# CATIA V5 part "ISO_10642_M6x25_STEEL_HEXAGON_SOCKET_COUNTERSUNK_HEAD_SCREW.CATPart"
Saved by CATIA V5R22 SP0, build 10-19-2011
Part number: ISO 10642 SCREW M6x25 STEEL HEXAGON SOCKET COUNTERSUNK HEAD
Publications: "Mating Edge", "Axis"
Bounding box of the stored display mesh (mm): x -25.42 to 0, y -6.719 to 6.719, z -6.714 to 6.714
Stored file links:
  D:\PER\CAO_PER_MODIF_2025\CAO_PER_pick&place_2024P\Sous_Ensemble_Boite\ISO_10642_M6x25_STEEL_HEXAGON_SOCKET_COUNTERSUNK_HEAD_SCREW.CATPart
  C:\Program Files\Dassault Systemes\B22\win_b64\startup\components\MechanicalStandardParts\EN_Standards\Design_Tables\EN_ISO_10642_HEXAGON_SOCKET_COUNTERSUNK_SCREW.txt
  C:\Program Files\Dassault Systemes\B22\win_b64\startup\components\MechanicalStandardParts\ISO_Standards\Design_Tables\ISO_10642_HEXAGON_SOCKET_COUNTERSUNK_SCREW.txt
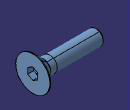
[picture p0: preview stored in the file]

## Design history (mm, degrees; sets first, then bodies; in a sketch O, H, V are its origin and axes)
Parameters
  l_length_nom = 25 mm
  b_ref = 24
  l_length_min = 24.58 mm
  l_length_max = 25.42 mm
  dk_head_dia_max = 13.44 mm
  dk_head_dia_min = 11.34 mm
  ls = 6.72 mm
  k_hed_depth = 3.72 mm
  r = 0.25 mm
  s_across_flats = 4 mm
  t_insert_depth = 2.2 mm
  d_dia = 6 mm
  threading = 18.28 mm
  p_pitch = 1 mm
Body1 "PartBody" (main body)
  Sketch1 on zx-plane, origin (0, 0, 0), H (-1, 0, 0), V (0, 0, 1)
    line L1 (0, 6.72) -> (0.3333, 6.72)
    point P2 (0.3333, 6.72)
    line L2 (0.3333, 6.72) -> (4.0533, 3)
    line L3 (4.0533, 3) -> (6.72, 3)
    line L4 (6.72, 3) -> (6.72, 2.9268)
    point P5 (6.72, 2.9268)
    line L5 (6.72, 2.9268) -> (24.8787, 2.9268)
    point P6 (24.8787, 2.9268)
    line L6 (24.8787, 2.9268) -> (25.42, 2.3855)
    axis line L7 (-30, 0) -> (125, 0)
    line L8 (25.42, 2.3855) -> (25.42, 0)
    point P10 (25.42, 0)
    line L9 (0, 6.72) -> (0, 0)
    distance L9 P5 = 6.72 {= ls}
    distance L9 L8 = 25.42 {= l_length_max}
    angle L5 L6 = 45
    distance L5 L7 = 2.9268 {= d_dia /2.05}
    distance L3 L7 = 3 {= d_dia  /2}
    angle L7 L2 = 45
    distance L1 L7 = 6.72 {= dk_head_dia_max /2}
    distance L9 P2 = 0.3333 {= p_pitch /3}
    distance P6 L8 = 0.5413 {= p_pitch *0.5413}
    horizontal: L1 H, L3 H, L5 H, L7 H
    vertical: L4 V, L9 V
    fix: L7
    coincidence: P10 L7
  Shaft1: profile Sketch1, axis Sketch1.L7, angle 360
  Body2
    Sketch2 on face of Shaft1, origin (0, 0, 0), H (0, 1, 0), V (0, 0, 1)
      point P1 (2, -1.1547)
      point P2 (2, 1.1547)
      point P3 (0, 2.3094)
      point P4 (-2, 1.1547)
      point P5 (-2, -1.1547)
      point P6 (0, -2.3094)
      point P7 (2, 0)
      line L1 (2, -1.1547) -> (2, 1.1547)
      line L2 (2, 1.1547) -> (0, 2.3094)
      line L3 (0, 2.3094) -> (-2, 1.1547)
      line L4 (-2, 1.1547) -> (-2, -1.1547)
      line L5 (-2, -1.1547) -> (0, -2.3094)
      line L6 (0, -2.3094) -> (2, -1.1547)
      construction line L7 (0, 0) -> (2, 0)
      construction circle A1 centre (0, 0) radius 2.3094
      construction arc A2 centre (-2, -1.1547) radius 2.3094 from (-2, 1.1547) to (0, -2.3094) cw
      construction arc A3 centre (2, 1.1547) radius 2.3094 from (0, 2.3094) to (2, -1.1547) ccw
      point P8 (-2, -1.1547)
      point P9 (2, 1.1547)
      distance L1 L4 = 4 {= s_across_flats}
      horizontal: L7 H
      coincidence: A1 P1, A1 P2, A1 P3, A1 P4, A1 P5, A1 P6, A2 P4, A2 P6, A2 O, P8 P5, A3 P3, A3 P1, A3 O, P9 P2
      midpoint: P7 L1
    Pad1: profile Sketch2, direction (-1, 0, 0), length 20
    Body3
      Sketch3 on zx-plane, origin (0, 0, 0), H (-1, 0, 0), V (0, 0, 1)
        line L1 (0, 0) -> (0, 2.3094)
        line L2 (0, 2.3094) -> (2.2, 2.3094)
        point P2 (2.2, 2.3094)
        line L3 (2.2, 2.3094) -> (3.5333, 0)
        point P3 (3.5333, 0)
        axis line L4 (-13.9938, 0) -> (46.4324, 0)
        reference projected line E1 (0, 2.3094) -> (20, 2.3094) from edge [face of Pad1 | face of Pad1]
        angle L3 L4 = 60
        distance L1 P2 = 2.2 {= t_insert_depth}
        vertical: L1 V
        horizontal: L2 H, L4 H
        fix: L4
        coincidence: L2 E1, P3 L4
      Shaft2: profile Sketch3, axis Sketch3.L4, angle 360
    Intersect1: tool Body3
  Remove1: tool Body2
  Fillet1: radius 0.25 {= r}, on edge [face of Shaft1 | face of Shaft1]
  Thread1: diameter 5.8537 {= d_dia /1.025}, depth 18.28 {= threading}, pitch 1, on face of Shaft1, from face of Shaft1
